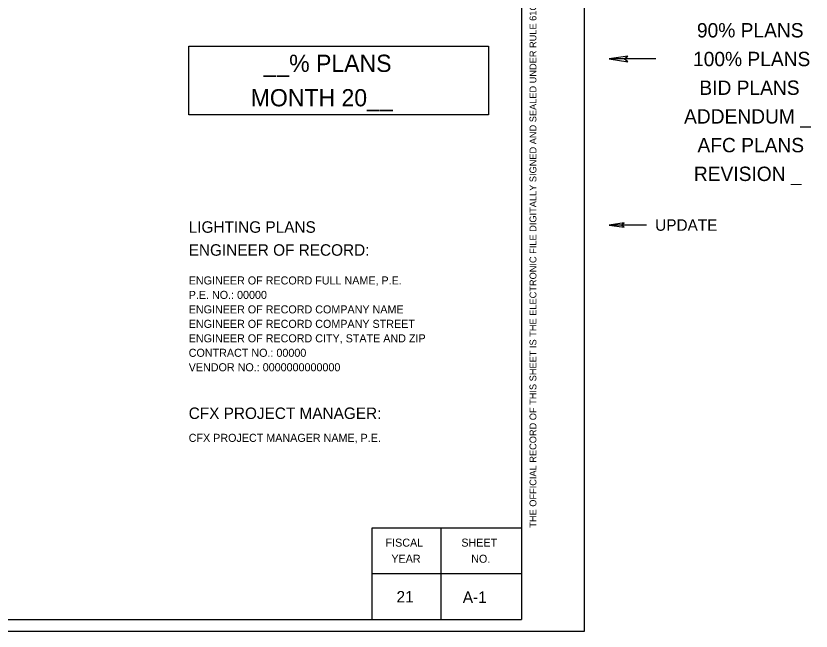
# Model space of a CAD drawing. Extents: x -830013.9 to -829988.1, y 1290300 to 1290310.6.
# Drawn here: x -829996.83 to -829989.9, y 1290299.98 to 1290305.33 of the extents above; entities that cross this region are included whole.
import ezdxf

# ---------------------------------------------------------------- set-up
doc = ezdxf.new("R2010")
doc.units = 0
for name, color, linetype in [('NonPlottingEle_dp', 7, 'Continuous'), ('PlotBorder_dp', 7, 'Continuous'), ('SheetBorder_dp', 7, 'Continuous'), ('SheetLines_dp', 7, 'Continuous'), ('TextLabel', 7, 'Continuous'), ('TextMisc', 7, 'Continuous'), ('TextNotes', 7, 'Continuous'), ('TextShtNo', 7, 'Continuous')]:
    doc.layers.add(name, color=color, linetype=linetype)

msp = doc.modelspace()

# ---------------------------------------------------------------- linework, layer by layer
at = {"layer": 'NonPlottingEle_dp'}
for p, q in [((-829991.4963, 1290304.9842), (-829991.6609, 1290304.9595)), ((-829991.6609, 1290304.9595), (-829991.4963, 1290304.9348)), ((-829991.255, 1290304.9595), (-829991.6609, 1290304.9595)), ((-829991.5293, 1290304.9595), (-829991.4963, 1290304.9842)), ((-829991.4963, 1290304.9348), (-829991.5293, 1290304.9595)), ((-829991.5293, 1290303.5333), (-829991.6609, 1290303.5136)), ((-829991.3362, 1290303.5136), (-829991.6609, 1290303.5136)), ((-829991.6609, 1290303.5136), (-829991.5293, 1290303.4938)), ((-829991.5556, 1290303.5136), (-829991.5293, 1290303.5333)), ((-829991.5293, 1290303.4938), (-829991.5556, 1290303.5136))]:
    msp.add_line(p, q, dxfattribs=at)
at = {"layer": 'PlotBorder_dp'}
msp.add_lwpolyline([(-830008.3742, 1290299.978), (-829991.8742, 1290299.978), (-829991.8742, 1290310.578), (-830008.3742, 1290310.578)], close=True, dxfattribs=at)
at = {"layer": 'SheetBorder_dp'}
for p in [(-829992.4242, 1290310.478), (-830007.8242, 1290300.078)]:
    msp.add_line(p, (-829992.4242, 1290300.078), dxfattribs=at)
at = {"layer": 'SheetLines_dp'}
for p, q in [((-829993.7242, 1290300.878), (-829992.4242, 1290300.878)), ((-829993.7242, 1290300.078), (-829993.7242, 1290300.878)), ((-829993.1242, 1290300.078), (-829993.1242, 1290300.878)), ((-829993.7242, 1290300.478), (-829992.4242, 1290300.478))]:
    msp.add_line(p, q, dxfattribs=at)
at = {"layer": 'TextLabel'}
msp.add_lwpolyline([(-829995.3242, 1290305.07), (-829992.7118, 1290305.07), (-829992.7118, 1290304.4744), (-829995.3242, 1290304.4744)], close=True, dxfattribs=at)

# ---------------------------------------------------------------- texts
at = {"layer": 'NonPlottingEle_dp'}
for s, height, p in [('90% PLANS', 0.125, (-829990.8954, 1290305.147)), ('100% PLANS', 0.125, (-829990.9294, 1290304.897)), ('BID PLANS', 0.125, (-829990.8742, 1290304.647)), ('ADDENDUM _', 0.125, (-829991.0076, 1290304.397)), ('AFC PLANS', 0.125, (-829990.8906, 1290304.147)), ('REVISION _', 0.125, (-829990.9219, 1290303.897)), ('UPDATE', 0.1, (-829991.2592, 1290303.4636))]:
    msp.add_text(s, height=height, dxfattribs=at).set_placement(p)
at = {"layer": 'TextLabel'}
for s, height, p in [('__% PLANS', 0.15, (-829994.6716, 1290304.8472)), ('MONTH 20__', 0.15, (-829994.7839, 1290304.5472)), ('LIGHTING PLANS', 0.1, (-829995.3242, 1290303.4463)), ('ENGINEER OF RECORD:', 0.1, (-829995.3242, 1290303.2463)), ('21', 0.1, (-829993.5129, 1290300.227))]:
    msp.add_text(s, height=height, dxfattribs=at).set_placement(p)
at = {"layer": 'TextMisc'}
msp.add_text('THE OFFICIAL RECORD OF THIS SHEET IS THE ELECTRONIC FILE DIGITALLY SIGNED AND SEALED UNDER RULE 61G15-23.004, F.A.C.', height=0.06, rotation=90, dxfattribs=at).set_placement((-829992.2942, 1290300.878))
at = {"layer": 'TextNotes'}
for s, height, p in [('ENGINEER OF RECORD FULL NAME, P.E.      ', 0.07, (-829995.3242, 1290302.9963)), ('P.E. NO.: 00000', 0.07, (-829995.3242, 1290302.8703)), ('ENGINEER OF RECORD COMPANY NAME         ', 0.07, (-829995.3242, 1290302.7443)), ('ENGINEER OF RECORD COMPANY STREET       ', 0.07, (-829995.3242, 1290302.6183)), ('ENGINEER OF RECORD CITY, STATE AND ZIP  ', 0.07, (-829995.3242, 1290302.4923)), ('CONTRACT NO.: 00000', 0.07, (-829995.3242, 1290302.3663)), ('VENDOR NO.: 0000000000000', 0.07, (-829995.3242, 1290302.2403)), ('CFX PROJECT MANAGER:', 0.1, (-829995.3242, 1290301.8248)), ('CFX PROJECT MANAGER NAME, P.E.          ', 0.07, (-829995.3242, 1290301.6257))]:
    msp.add_text(s, height=height, dxfattribs=at).set_placement(p)
for s, p in [('FISCAL', (-829993.6087, 1290300.7135)), ('SHEET', (-829992.9484, 1290300.7135)), ('YEAR', (-829993.558, 1290300.5734)), ('NO.', (-829992.8627, 1290300.5733))]:
    msp.add_text(s, height=0.07, rotation=359.86066, dxfattribs=at).set_placement(p)
at = {"layer": 'TextShtNo'}
msp.add_text(' A-1 ', height=0.1, dxfattribs=at).set_placement((-829992.9727, 1290300.2237))

doc.saveas('drawing.dxf')
